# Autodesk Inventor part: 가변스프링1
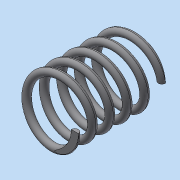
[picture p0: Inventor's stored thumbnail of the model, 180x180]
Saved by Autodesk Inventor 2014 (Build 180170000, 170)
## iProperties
Created: 2018-10
Part Number: 가변스프링1
Material: Generic
Document SubType Name: Modeling
Designer: kb542
Density: 1 g/cm^3
Appearance: Default
Mass: 0.775705 g
Surface Area: 15.7757 cm^2
Volume: 0.775705 cm^3
Author: kb542
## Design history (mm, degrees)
sketch "스케치1"
  geometry: L1 (0, 0)-(8, 0); L2 (8, 0)-(8, 24.528); L3 (8, 24.528)-(0, 24.528); L4 (0, 24.528)-(0, 0); C1 r 1 at (8, 0)
  constraints: 8 end point, 2 parallel, 1 centre point, 1 coincident, 1 horizontal, 1 perpendicular
  dimensions: "d0" = 24.52794 distance between parallel lines of L1 L3 (derived); "d1" = 2 diameter of C1; "d2" = 16 diameter of L2 L4
feature "코일1" sketch "스케치1" pitch "d3" = 10; turns "d5" = 5; dims "d4" = 24.52794 (= d0), "d6" = 0, angle "d7" = 90 deg, angle "d8" = 90 deg, "d9" = 0, "d10" = 0
sketch "스케치2"
  geometry: L1 (-9, 0)-(-7, 0) reference; 1 further point
  constraints: 1 horizontal alignment
extrude "돌출1" cut sketch "스케치2" distance "d11" = 10; taper "d12" = 0 deg
node "작업 평면1"
sketch "스케치3"
  geometry: L1 (-7, 0)-(-9, 0) reference; 1 further point
  constraints: 1 horizontal alignment
extrude "돌출2" cut sketch "스케치3" distance "d13" = 10; taper "d14" = 0 deg
node "솔리드1"
node "절단 모서리 투영1"
node "절단 모서리 투영2"
